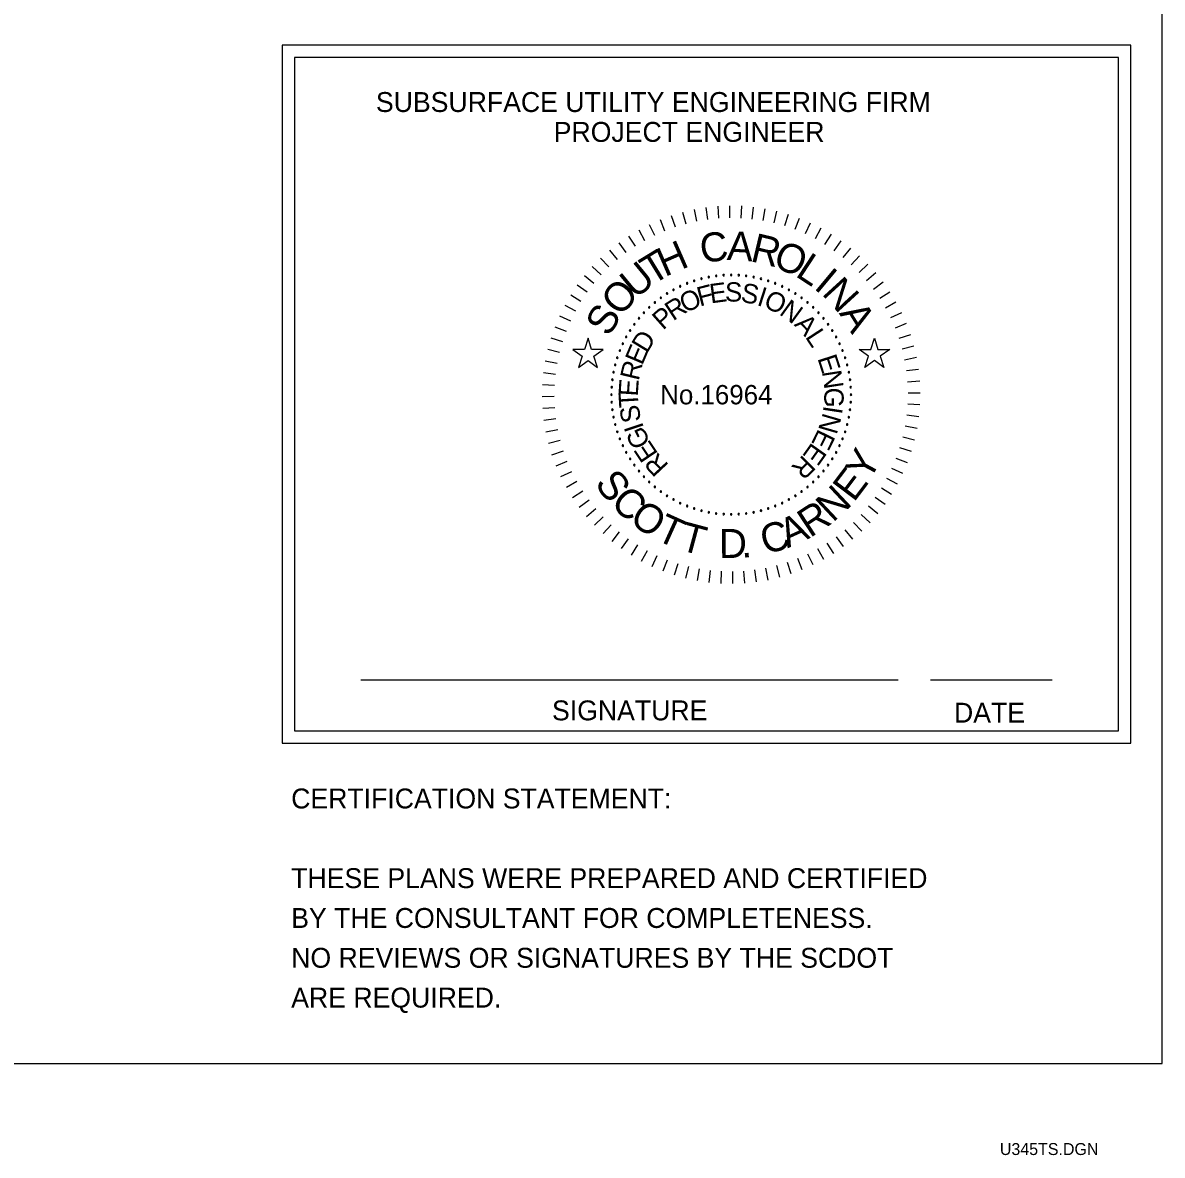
# Model space of a CAD drawing. Extents: x 190073 to 191750, y 195724 to 196797.
# Drawn here: x 191461.5 to 191747.6, y 195724.1 to 196008.5 of the extents above; entities that cross this region are included whole.
import ezdxf

# ---------------------------------------------------------------- set-up
doc = ezdxf.new("R2010")
doc.units = 0
doc.layers.add('RD_SHT_Bndy', color=7, linetype='Continuous')
doc.layers.add('RD_SHT_TX', color=7, linetype='Continuous')

# ---------------------------------------------------------------- blocks, each defined once
blk = doc.blocks.new('SDCSCSEAL')
for p, q in [((-0.5883, 0.222), (-0.6035, 0.1753)), ((-0.5732, 0.1753), (-0.5883, 0.222)), ((0.6013, 0.1753), (0.6165, 0.222)), ((0.6165, 0.222), (0.6317, 0.1753)), ((-0.6527, 0.1753), (-0.6129, 0.1464)), ((-0.6035, 0.1753), (-0.6527, 0.1753)), ((-0.6129, 0.1464), (-0.6281, 0.0996)), ((-0.524, 0.1753), (-0.5732, 0.1753)), ((-0.5638, 0.1464), (-0.524, 0.1753)), ((-0.5486, 0.0996), (-0.5638, 0.1464)), ((0.5919, 0.1464), (0.5521, 0.1753)), ((0.5521, 0.1753), (0.6013, 0.1753)), ((0.5767, 0.0996), (0.5919, 0.1464)), ((0.6317, 0.1753), (0.6809, 0.1753)), ((0.6809, 0.1753), (0.6411, 0.1464)), ((0.6411, 0.1464), (0.6563, 0.0996)), ((-0.6281, 0.0996), (-0.5883, 0.1285)), ((-0.5883, 0.1285), (-0.5486, 0.0996)), ((0.6165, 0.1285), (0.5767, 0.0996)), ((0.6563, 0.0996), (0.6165, 0.1285))]:
    blk.add_line(p, q)
for points in [[(-0.0925, 0.7725), (-0.0857, 0.7221)], [(-0.0428, 0.7776), (-0.0392, 0.7269)], [(0.0071, 0.7796), (0.0075, 0.7287)], [(0.057, 0.7785), (0.0543, 0.7277)], [(0.1068, 0.7742), (0.1008, 0.7237)], [(-0.2851, 0.7212), (-0.266, 0.6741)], [(-0.2383, 0.7386), (-0.2221, 0.6903)], [(-0.1904, 0.7529), (-0.1773, 0.7037)], [(-0.1418, 0.7642), (-0.1318, 0.7143)], [(0.1562, 0.7669), (0.1471, 0.7168)], [(0.205, 0.7564), (0.1928, 0.707)], [(0.2531, 0.7429), (0.2378, 0.6944)], [(0.3002, 0.7264), (0.2819, 0.6789)], [(-0.3751, 0.6779), (-0.3502, 0.6335)], [(-0.3308, 0.701), (-0.3087, 0.6551)], [(0.3463, 0.7069), (0.325, 0.6607)], [(0.391, 0.6847), (0.3668, 0.6399)], [(-0.4589, 0.6237), (-0.4286, 0.5828)], [(-0.4179, 0.6521), (-0.3902, 0.6094)], [(0.4342, 0.6596), (0.4073, 0.6164)], [(0.4757, 0.6319), (0.4462, 0.5905)], [(-0.4981, 0.5927), (-0.4653, 0.5538)], [(0.5155, 0.6016), (0.4834, 0.5622)], [(-0.5353, 0.5593), (-0.5001, 0.5226)], [(0.5532, 0.5689), (0.5187, 0.5315)], [(0.5889, 0.5339), (0.5521, 0.4988)], [(-0.603, 0.486), (-0.5635, 0.4539)], [(-0.5703, 0.5237), (-0.5329, 0.4892)], [(0.6222, 0.4968), (0.5833, 0.464)], [(-0.6333, 0.4462), (-0.5918, 0.4167)], [(0.6532, 0.4576), (0.6123, 0.4273)], [(-0.661, 0.4047), (-0.6178, 0.3778)], [(0.6816, 0.4165), (0.6389, 0.3889)], [(-0.686, 0.3614), (-0.6412, 0.3373)], [(0.7074, 0.3737), (0.663, 0.3488)], [(-0.7083, 0.3167), (-0.6621, 0.2955)], [(0.7305, 0.3294), (0.6846, 0.3074)], [(-0.7277, 0.2707), (-0.6803, 0.2524)], [(0.7507, 0.2838), (0.7036, 0.2646)], [(-0.7442, 0.2236), (-0.6957, 0.2083)], [(0.7681, 0.2369), (0.7198, 0.2208)], [(-0.7577, 0.1755), (-0.7084, 0.1633)], [(0.7824, 0.1891), (0.7332, 0.176)], [(-0.7682, 0.1267), (-0.7181, 0.1176)], [(0.7937, 0.1404), (0.7438, 0.1305)], [(-0.7756, 0.0773), (-0.7251, 0.0713)], [(0.802, 0.0912), (0.7516, 0.0844)], [(-0.7799, 0.0275), (-0.729, 0.0247)], [(0.8071, 0.0415), (0.7564, 0.0378)], [(-0.781, -0.0224), (-0.7301, -0.022)], [(0.8091, -0.0084), (0.7583, -0.0089)], [(-0.779, -0.0724), (-0.7282, -0.0687)], [(0.808, -0.0584), (0.7572, -0.0556)], [(-0.7738, -0.122), (-0.7234, -0.1152)], [(0.8038, -0.1081), (0.7532, -0.1022)], [(-0.7656, -0.1713), (-0.7157, -0.1613)], [(0.7964, -0.1575), (0.7463, -0.1484)], [(-0.7543, -0.2199), (-0.7051, -0.2069)], [(0.7724, -0.2545), (0.7239, -0.2392)], [(0.7859, -0.2064), (0.7365, -0.1941)], [(-0.7399, -0.2678), (-0.6916, -0.2516)], [(0.7559, -0.3016), (0.7084, -0.2833)], [(-0.7226, -0.3146), (-0.6754, -0.2955)], [(0.7365, -0.3476), (0.6902, -0.3263)], [(-0.7023, -0.3603), (-0.6565, -0.3382)], [(-0.6793, -0.4046), (-0.6349, -0.3797)], [(0.7142, -0.3923), (0.6694, -0.3682)], [(-0.6535, -0.4474), (-0.6107, -0.4197)], [(0.6891, -0.4355), (0.6459, -0.4086)], [(-0.625, -0.4884), (-0.5841, -0.4582)], [(0.6614, -0.4771), (0.62, -0.4475)], [(-0.5941, -0.5276), (-0.5551, -0.4948)], [(0.5985, -0.5546), (0.5611, -0.5201)], [(0.6312, -0.5168), (0.5917, -0.4847)], [(-0.5607, -0.5648), (-0.5239, -0.5296)], [(-0.5251, -0.5998), (-0.4906, -0.5624)], [(0.5634, -0.5902), (0.5283, -0.5534)], [(-0.4873, -0.6325), (-0.4552, -0.593)], [(-0.4476, -0.6628), (-0.418, -0.6213)], [(0.4871, -0.6545), (0.4568, -0.6136)], [(0.5263, -0.6236), (0.4935, -0.5846)], [(-0.406, -0.6905), (-0.3791, -0.6473)], [(-0.3628, -0.7155), (-0.3387, -0.6707)], [(0.4032, -0.7088), (0.3783, -0.6644)], [(0.446, -0.683), (0.4184, -0.6402)], [(-0.3181, -0.7378), (-0.2968, -0.6916)], [(-0.2721, -0.7572), (-0.2538, -0.7098)], [(0.3133, -0.7521), (0.2941, -0.7049)], [(0.3589, -0.7318), (0.3369, -0.686)], [(-0.2249, -0.7737), (-0.2096, -0.7252)], [(-0.1769, -0.7873), (-0.1646, -0.7379)], [(-0.128, -0.7977), (-0.1189, -0.7477)], [(-0.0786, -0.8051), (-0.0727, -0.7546)], [(-0.0288, -0.8094), (-0.0261, -0.7586)], [(0.0211, -0.8105), (0.0206, -0.7596)], [(0.071, -0.8085), (0.0674, -0.7577)], [(0.1207, -0.8033), (0.1139, -0.7529)], [(0.1699, -0.7951), (0.16, -0.7452)], [(0.2186, -0.7838), (0.2055, -0.7346)], [(0.2664, -0.7694), (0.2503, -0.7212)]]:
    blk.add_lwpolyline(points)
for centre, start, end in [((-0.0803, 0.4794), 100.8, 280.8), ((-0.0803, 0.4794), 280.8, 100.8), ((-0.0491, 0.4844), 97.2, 277.2), ((-0.0491, 0.4844), 277.2, 97.2), ((-0.0176, 0.4873), 93.6, 273.6), ((-0.0176, 0.4873), 273.6, 93.6), ((0.0141, 0.4883), 90, 270), ((0.0141, 0.4883), 270, 90), ((0.0457, 0.4873), 86.4, 266.4), ((0.0457, 0.4873), 266.4, 86.4), ((0.0772, 0.4844), 82.8, 262.8), ((0.0772, 0.4844), 262.8, 82.8), ((0.1085, 0.4794), 79.2, 259.2), ((0.1085, 0.4794), 259.2, 79.2), ((-0.2004, 0.4404), 115.2, 295.2), ((-0.2004, 0.4404), 295.2, 115.2), ((-0.1714, 0.453), 111.6, 291.6), ((-0.1714, 0.453), 291.6, 111.6), ((-0.1416, 0.4637), 108, 288), ((-0.1416, 0.4637), 288, 108), ((-0.1112, 0.4725), 104.4, 284.4), ((-0.1112, 0.4725), 284.4, 104.4), ((0.1394, 0.4725), 75.6, 255.6), ((0.1394, 0.4725), 255.6, 75.6), ((0.1698, 0.4637), 72, 252), ((0.1698, 0.4637), 252, 72), ((0.1995, 0.453), 68.4, 248.4), ((0.1995, 0.453), 248.4, 68.4), ((0.2286, 0.4404), 64.8, 244.8), ((0.2286, 0.4404), 244.8, 64.8), ((-0.282, 0.3921), 126, 306), ((-0.282, 0.3921), 306, 126), ((-0.2559, 0.4099), 122.4, 302.4), ((-0.2559, 0.4099), 302.4, 122.4), ((-0.2286, 0.426), 118.8, 298.8), ((-0.2286, 0.426), 298.8, 118.8), ((0.2568, 0.426), 61.2, 241.2), ((0.2568, 0.426), 241.2, 61.2), ((0.284, 0.4099), 57.6, 237.6), ((0.284, 0.4099), 237.6, 57.6), ((0.3102, 0.3921), 54, 234), ((0.3102, 0.3921), 234, 54), ((-0.3308, 0.3518), 133.2, 313.2), ((-0.3308, 0.3518), 313.2, 133.2), ((-0.307, 0.3727), 129.6, 309.6), ((-0.307, 0.3727), 309.6, 129.6), ((0.3352, 0.3727), 50.4, 230.4), ((0.3352, 0.3727), 230.4, 50.4), ((0.3589, 0.3518), 46.8, 226.8), ((0.3589, 0.3518), 226.8, 46.8), ((-0.3741, 0.3057), 140.4, 320.4), ((-0.3741, 0.3057), 320.4, 140.4), ((-0.3532, 0.3294), 136.8, 316.8), ((-0.3532, 0.3294), 316.8, 136.8), ((0.3813, 0.3294), 43.2, 223.2), ((0.3813, 0.3294), 223.2, 43.2), ((0.4022, 0.3057), 39.6, 219.6), ((0.4022, 0.3057), 219.6, 39.6), ((-0.4113, 0.2545), 147.6, 327.6), ((-0.4113, 0.2545), 327.6, 147.6), ((-0.3935, 0.2807), 144, 324), ((-0.3935, 0.2807), 324, 144), ((0.4216, 0.2807), 36, 216), ((0.4216, 0.2807), 216, 36), ((0.4394, 0.2545), 32.4, 212.4), ((0.4394, 0.2545), 212.4, 32.4), ((-0.4417, 0.1991), 154.8, 334.8), ((-0.4417, 0.1991), 334.8, 154.8), ((-0.4274, 0.2273), 151.2, 331.2), ((-0.4274, 0.2273), 331.2, 151.2), ((0.4555, 0.2273), 28.8, 208.8), ((0.4555, 0.2273), 208.8, 28.8), ((0.4699, 0.1991), 25.2, 205.2), ((0.4699, 0.1991), 205.2, 25.2), ((-0.4543, 0.17), 158.4, 338.4), ((-0.4543, 0.17), 338.4, 158.4), ((0.4825, 0.17), 21.6, 201.6), ((0.4825, 0.17), 201.6, 21.6), ((-0.4739, 0.1099), 165.6, 345.6), ((-0.4739, 0.1099), 345.6, 165.6), ((-0.465, 0.1402), 162, 342), ((-0.465, 0.1402), 342, 162), ((0.4932, 0.1402), 18, 198), ((0.4932, 0.1402), 198, 18), ((0.502, 0.1099), 14.4, 194.4), ((0.502, 0.1099), 194.4, 14.4), ((-0.4857, 0.0477), 352.8, 172.8), ((-0.4857, 0.0477), 172.8, 352.8), ((-0.4808, 0.079), 349.2, 169.2), ((-0.4808, 0.079), 169.2, 349.2), ((0.5089, 0.079), 10.8, 190.8), ((0.5089, 0.079), 190.8, 10.8), ((0.5139, 0.0477), 7.2, 187.2), ((0.5139, 0.0477), 187.2, 7.2), ((-0.4887, 0.0162), 356.4, 176.4), ((-0.4887, 0.0162), 176.4, 356.4), ((0.5169, 0.0162), 3.6, 183.6), ((0.5169, 0.0162), 183.6, 3.6), ((-0.4897, -0.0154), 0, 180), ((-0.4897, -0.0154), 180, 0), ((-0.4887, -0.0471), 3.6, 183.6), ((-0.4887, -0.0471), 183.6, 3.6), ((0.5169, -0.0471), 356.4, 176.4), ((0.5169, -0.0471), 176.4, 356.4), ((0.5179, -0.0154), 0, 180), ((0.5179, -0.0154), 180, 0), ((-0.4857, -0.0786), 7.2, 187.2), ((-0.4857, -0.0786), 187.2, 7.2), ((0.5139, -0.0786), 352.8, 172.8), ((0.5139, -0.0786), 172.8, 352.8), ((-0.4808, -0.1098), 10.8, 190.8), ((-0.4808, -0.1098), 190.8, 10.8), ((-0.4739, -0.1407), 14.4, 194.4), ((-0.4739, -0.1407), 194.4, 14.4), ((0.502, -0.1407), 165.6, 345.6), ((0.502, -0.1407), 345.6, 165.6), ((0.5089, -0.1098), 169.2, 349.2), ((0.5089, -0.1098), 349.2, 169.2), ((-0.465, -0.1711), 18, 198), ((-0.465, -0.1711), 198, 18), ((0.4932, -0.1711), 162, 342), ((0.4932, -0.1711), 342, 162), ((-0.4543, -0.2009), 21.6, 201.6), ((-0.4543, -0.2009), 201.6, 21.6), ((-0.4417, -0.2299), 25.2, 205.2), ((-0.4417, -0.2299), 205.2, 25.2), ((0.4699, -0.2299), 154.8, 334.8), ((0.4699, -0.2299), 334.8, 154.8), ((0.4825, -0.2009), 158.4, 338.4), ((0.4825, -0.2009), 338.4, 158.4), ((-0.4274, -0.2581), 28.8, 208.8), ((-0.4274, -0.2581), 208.8, 28.8), ((-0.4113, -0.2854), 32.4, 212.4), ((-0.4113, -0.2854), 212.4, 32.4), ((0.4394, -0.2854), 147.6, 327.6), ((0.4394, -0.2854), 327.6, 147.6), ((0.4555, -0.2581), 151.2, 331.2), ((0.4555, -0.2581), 331.2, 151.2), ((-0.3935, -0.3115), 36, 216), ((-0.3935, -0.3115), 216, 36), ((-0.3741, -0.3365), 39.6, 219.6), ((-0.3741, -0.3365), 219.6, 39.6), ((0.4022, -0.3365), 140.4, 320.4), ((0.4022, -0.3365), 320.4, 140.4), ((0.4216, -0.3115), 144, 324), ((0.4216, -0.3115), 324, 144), ((-0.3532, -0.3603), 43.2, 223.2), ((-0.3532, -0.3603), 223.2, 43.2), ((-0.3308, -0.3827), 46.8, 226.8), ((-0.3308, -0.3827), 226.8, 46.8), ((0.3589, -0.3827), 133.2, 313.2), ((0.3589, -0.3827), 313.2, 133.2), ((0.3813, -0.3603), 136.8, 316.8), ((0.3813, -0.3603), 316.8, 136.8), ((-0.307, -0.4036), 50.4, 230.4), ((-0.307, -0.4036), 230.4, 50.4), ((-0.282, -0.423), 54, 234), ((-0.282, -0.423), 234, 54), ((0.3102, -0.423), 126, 306), ((0.3102, -0.423), 306, 126), ((0.3352, -0.4036), 129.6, 309.6), ((0.3352, -0.4036), 309.6, 129.6), ((-0.2559, -0.4408), 57.6, 237.6), ((-0.2559, -0.4408), 237.6, 57.6), ((-0.2286, -0.4569), 61.2, 241.2), ((-0.2286, -0.4569), 241.2, 61.2), ((-0.2004, -0.4713), 64.8, 244.8), ((-0.2004, -0.4713), 244.8, 64.8), ((0.2286, -0.4713), 115.2, 295.2), ((0.2286, -0.4713), 295.2, 115.2), ((0.2568, -0.4569), 118.8, 298.8), ((0.2568, -0.4569), 298.8, 118.8), ((0.284, -0.4408), 122.4, 302.4), ((0.284, -0.4408), 302.4, 122.4), ((-0.1714, -0.4838), 68.4, 248.4), ((-0.1714, -0.4838), 248.4, 68.4), ((-0.1416, -0.4945), 72, 252), ((-0.1416, -0.4945), 252, 72), ((-0.1112, -0.5034), 75.6, 255.6), ((-0.1112, -0.5034), 255.6, 75.6), ((-0.0803, -0.5103), 79.2, 259.2), ((-0.0803, -0.5103), 259.2, 79.2), ((-0.0491, -0.5152), 82.8, 262.8), ((-0.0491, -0.5152), 262.8, 82.8), ((-0.0176, -0.5182), 86.4, 266.4), ((-0.0176, -0.5182), 266.4, 86.4), ((0.0141, -0.5192), 90, 270), ((0.0141, -0.5192), 270, 90), ((0.0457, -0.5182), 93.6, 273.6), ((0.0457, -0.5182), 273.6, 93.6), ((0.0772, -0.5152), 97.2, 277.2), ((0.0772, -0.5152), 277.2, 97.2), ((0.1085, -0.5103), 100.8, 280.8), ((0.1085, -0.5103), 280.8, 100.8), ((0.1394, -0.5034), 104.4, 284.4), ((0.1394, -0.5034), 284.4, 104.4), ((0.1698, -0.4945), 108, 288), ((0.1698, -0.4945), 288, 108), ((0.1995, -0.4838), 111.6, 291.6), ((0.1995, -0.4838), 291.6, 111.6)]:
    blk.add_arc(centre, 0.00318, start, end)
for s, height, rotation, p in [('C', 0.1221, 7.0754, (-0.11, 0.5383)), ('H', 0.1221, 23.618, (-0.265, 0.479)), ('A', 0.1221, 356.6834, (-0.0055, 0.5515)), ('R', 0.1221, 346.6446, (0.0911, 0.5468)), ('O', 0.1221, 336.7814, (0.1838, 0.5264)), ('T', 0.1221, 31.4783, (-0.3188, 0.4431)), ('L', 0.1221, 326.7613, (0.2799, 0.4857)), ('U', 0.1221, 39.4378, (-0.3892, 0.3842)), ('I', 0.1221, 320.1414, (0.358, 0.4332)), ('N', 0.1221, 312.4699, (0.3918, 0.4084)), ('O', 0.1221, 49.2558, (-0.4514, 0.3096)), ('F', 0.0814, 14.5435, (-0.1181, 0.3551)), ('E', 0.0814, 7.5153, (-0.0718, 0.3685)), ('S', 0.0814, 358.8364, (-0.0128, 0.377)), ('S', 0.0814, 349.5361, (0.0509, 0.3762)), ('I', 0.0814, 342.2278, (0.1187, 0.3625)), ('R', 0.0814, 33.067, (-0.2304, 0.2929)), ('O', 0.0814, 24.0454, (-0.1806, 0.3268)), ('O', 0.0814, 334.9076, (0.1455, 0.3557)), ('N', 0.0814, 324.1079, (0.2127, 0.3245)), ('S', 0.1221, 59.6913, (-0.5, 0.2244)), ('P', 0.0814, 41.5108, (-0.273, 0.2537)), ('A', 0.1221, 301.8617, (0.4662, 0.3272)), ('A', 0.0814, 313.1487, (0.2761, 0.278)), ('D', 0.0814, 58.6546, (-0.3405, 0.1556)), ('L', 0.0814, 303.1023, (0.3233, 0.2278)), ('E', 0.0814, 67.0258, (-0.3603, 0.1054)), ('E', 0.0814, 287.8582, (0.3763, 0.1379)), ('R', 0.0814, 76.5028, (-0.3755, 0.0404)), ('N', 0.0814, 278.6824, (0.3956, 0.0817)), ('E', 0.0814, 86.1669, (-0.3792, -0.0241)), ('G', 0.0814, 269.102, (0.4064, 0.0151)), ('T', 0.0814, 93.42, (-0.3753, -0.0684)), ('S', 0.0814, 101.0311, (-0.3638, -0.1247)), ('I', 0.0814, 261.3077, (0.4038, -0.0591)), ('I', 0.0814, 108.5149, (-0.3525, -0.1547)), ('N', 0.0814, 253.7908, (0.401, -0.088)), ('G', 0.0814, 115.6476, (-0.3233, -0.2181)), ('E', 0.0814, 244.0055, (0.3816, -0.1558)), ('E', 0.0814, 123.9666, (-0.2914, -0.2633)), ('E', 0.0814, 234.7083, (0.3541, -0.2133)), ('Y', 0.1221, 61.7376, (0.5952, -0.3841)), ('R', 0.0814, 133.4172, (-0.2453, -0.3113)), ('R', 0.0814, 225.134, (0.3176, -0.2659)), ('E', 0.1221, 52.9175, (0.5301, -0.471)), ('S', 0.1221, 307.3739, (-0.5636, -0.3909)), ('C', 0.1221, 316.5316, (-0.4984, -0.4762)), ('N', 0.1221, 43.1563, (0.442, -0.5559)), ('O', 0.1221, 325.8349, (-0.4194, -0.5516)), ('R', 0.1221, 33.3373, (0.3457, -0.6195)), ('T', 0.1221, 335.7437, (-0.3087, -0.6235)), ('A', 0.1221, 24.4763, (0.2511, -0.6623)), ('T', 0.1221, 344.954, (-0.2072, -0.6674)), ('C', 0.1221, 16.6218, (0.1579, -0.6894)), ('D', 0.1221, 0.5326, (-0.0371, -0.7029)), ('.', 0.1221, 6.1742, (0.0585, -0.7025))]:
    blk.add_text(s, height=height, rotation=rotation).set_placement(p)
blk.add_text('No.16964', height=0.08142).set_placement((-0.2845, -0.0561))

msp = doc.modelspace()

# ---------------------------------------------------------------- linework, layer by layer
at = {"layer": 'RD_SHT_Bndy'}
for p, q in [((191747.56, 195747.12), (191747.56, 196797.12)), ((190072.56, 195747.12), (191747.56, 195747.12))]:
    msp.add_line(p, q, dxfattribs=at)
for points in [[(191526.6, 195827.56), (191739.67, 195827.56), (191739.67, 196002.83), (191526.6, 196002.83)], [(191529.69, 195830.66), (191736.58, 195830.66), (191736.58, 195999.74), (191529.69, 195999.74)]]:
    msp.add_lwpolyline(points, close=True, dxfattribs=at)
at = {"layer": 'RD_SHT_TX'}
for p, q in [((191546.32, 195843.52), (191681.28, 195843.52)), ((191689.4, 195843.52), (191719.95, 195843.52))]:
    msp.add_line(p, q, dxfattribs=at)

# ---------------------------------------------------------------- block references
at = {"xscale": 59.67872180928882, "yscale": 59.67872180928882}
msp.add_blockref('SDCSCSEAL', (191638.5, 195916), dxfattribs=at)

# ---------------------------------------------------------------- texts
at = {"layer": 'RD_SHT_TX'}
for s, height, p in [('SUBSURFACE UTILITY ENGINEERING FIRM', 5, (191550.14, 195986.06)), ('PROJECT ENGINEER', 5, (191594.78, 195978.56)), ('SIGNATURE', 5, (191594.35, 195833.31)), ('DATE', 5, (191695.28, 195832.73)), ('CERTIFICATION STATEMENT:', 5, (191528.87, 195811.19)), ('THESE PLANS WERE PREPARED AND CERTIFIED', 5, (191528.87, 195791.19)), ('BY THE CONSULTANT FOR COMPLETENESS.', 5, (191528.87, 195781.19)), ('NO REVIEWS OR SIGNATURES BY THE SCDOT', 5, (191528.87, 195771.19)), ('ARE REQUIRED.', 5, (191528.87, 195761.19)), ('U345TS.DGN', 3, (191706.8, 195724.17))]:
    msp.add_text(s, height=height, dxfattribs=at).set_placement(p)

doc.saveas('drawing.dxf')
